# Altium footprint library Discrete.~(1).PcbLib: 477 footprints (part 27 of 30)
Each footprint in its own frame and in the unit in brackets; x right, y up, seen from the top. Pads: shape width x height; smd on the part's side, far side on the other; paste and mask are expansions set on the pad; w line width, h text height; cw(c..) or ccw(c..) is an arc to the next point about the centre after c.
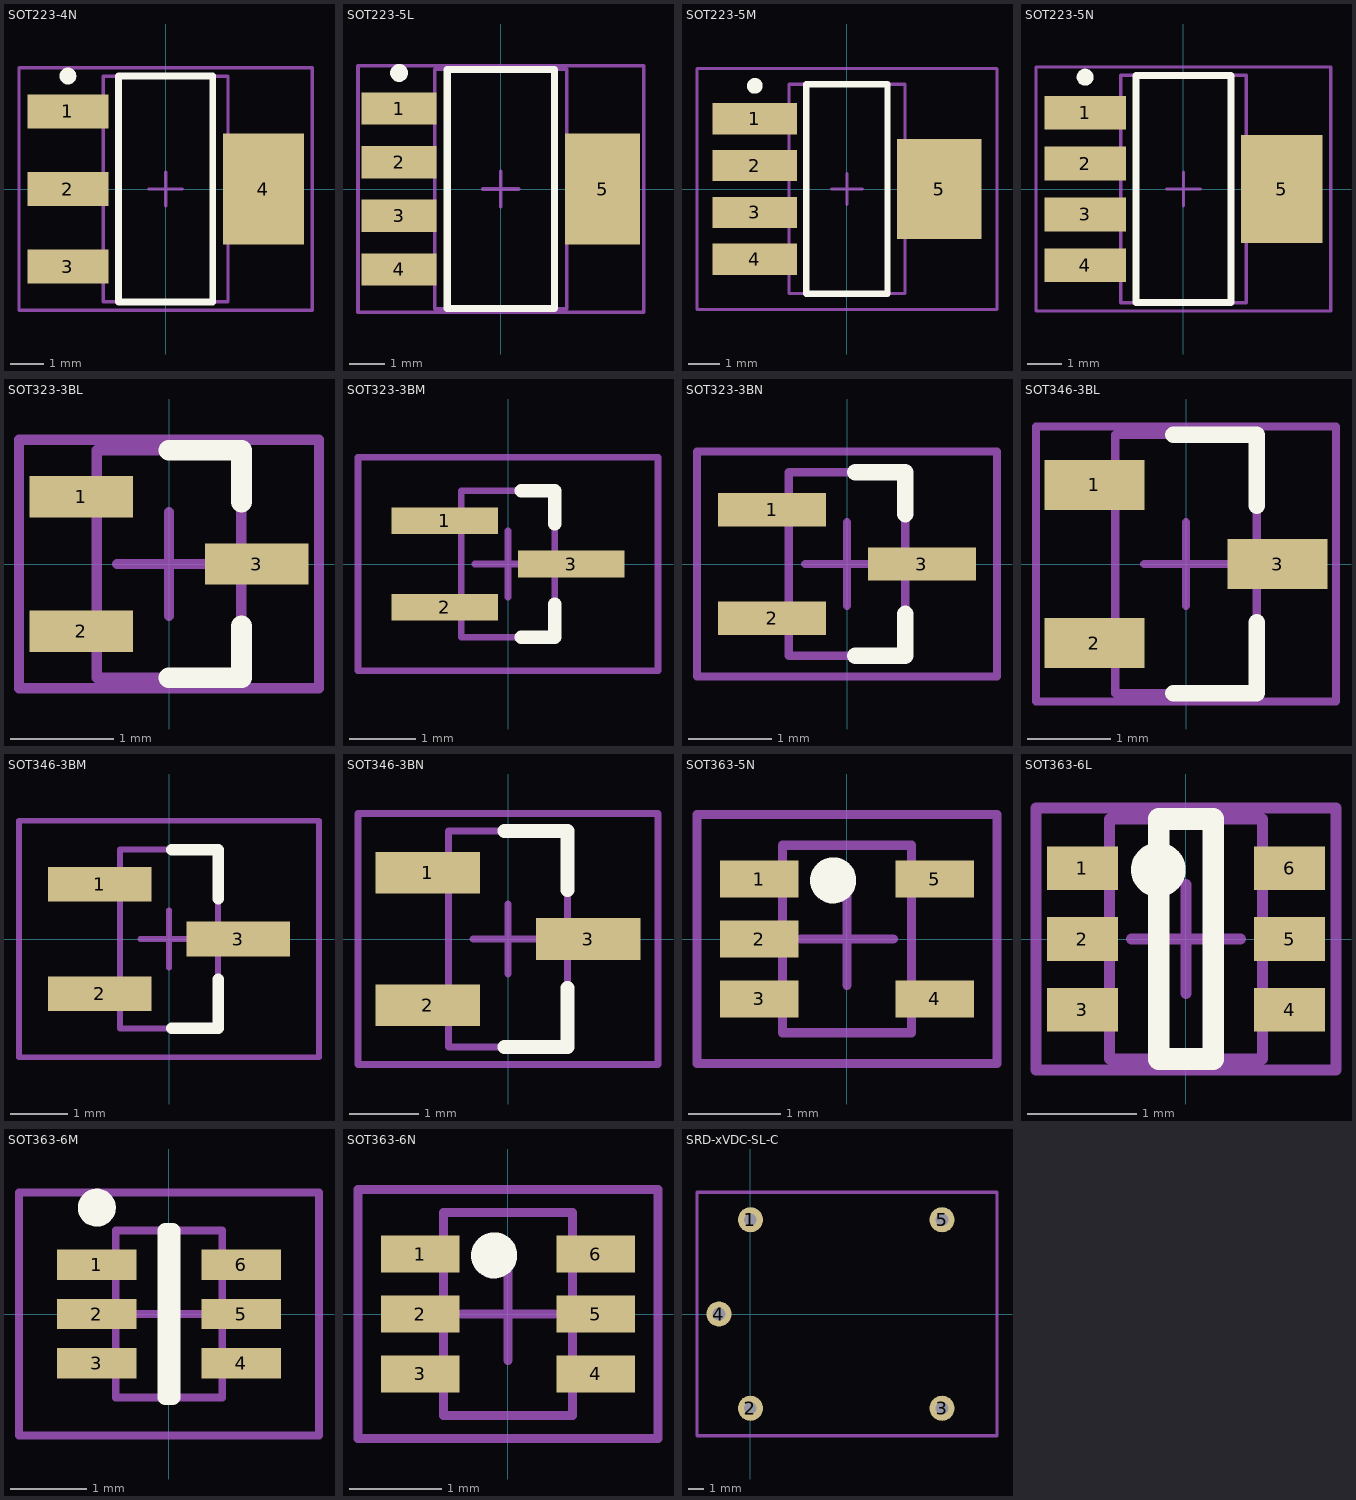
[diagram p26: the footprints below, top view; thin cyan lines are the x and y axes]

## SOT223-4N [mm] "SOT223/SC73, 4-Leads, Body 6.5x3.5mm, Pitch 2.3mm, Lead Span 7mm, IPC Medium Density"
height 1.8
pads (4):
  rect 2.4x1 smd: 1(-2.9,2.3) 2(-2.9,0) 3(-2.9,-2.3)
  rect 2.4x3.3 smd: 4(2.9,0)
Top Overlay:
  circle w0.25: c-2.9,3.35 r0.125
  lines w0.2: -1.4,-3.35 -1.4,3.35 1.4,3.35 1.4,-3.35 -1.4,-3.35
Mechanical 13:
  lines w0.1: -1.85,-3.35 -1.85,3.35 1.85,3.35 1.85,-3.35 -1.85,-3.35
Mechanical 15:
  lines w0.1: -0.5,0 0.5,0 ; 0,-0.5 0,0.5 ; -4.35,-3.6 -4.35,3.6 4.35,3.6 4.35,-3.6 -4.35,-3.6
3D body "SOT223.STEP": height 1.74, standoff 0.09, extent -3.551,-3.275 3.449,3.225

## SOT223-5L [mm] "SOT223, 5-Leads, Body 6.5x3.5mm, Pitch 1.5mm, Lead Span 7mm, IPC High Density"
height 1.8
pads (5):
  rect 2.1x0.9 smd: 1(-2.85,2.25) 2(-2.85,0.75) 3(-2.85,-0.75) 4(-2.85,-2.25)
  rect 2.1x3.1 smd: 5(2.85,0)
Top Overlay:
  circle w0.25: c-2.85,3.25 r0.125
  lines w0.2: -1.5,-3.35 1.5,-3.35 1.5,3.35 -1.5,3.35 -1.5,-3.35
Mechanical 13:
  lines w0.1: -1.85,-3.35 1.85,-3.35 1.85,3.35 -1.85,3.35 -1.85,-3.35
Mechanical 15:
  lines w0.1: -0.5,0 0.5,0 ; 0,-0.5 0,0.5 ; -4,-3.45 4,-3.45 4,3.45 -4,3.45 -4,-3.45
3D body: height 1.8, standoff 0, extent -1.85,-3.35 1.85,3.35

## SOT223-5M [mm] "SOT223, 5-Leads, Body 6.5x3.5mm, Pitch 1.5mm, Lead Span 7mm, IPC Low Density"
height 1.8
pads (5):
  rect 2.7x1 smd: 1(-2.95,2.25) 2(-2.95,0.75) 3(-2.95,-0.75) 4(-2.95,-2.25)
  rect 2.7x3.2 smd: 5(2.95,0)
Top Overlay:
  circle w0.25: c-2.95,3.3 r0.125
  lines w0.2: -1.3,-3.35 -1.3,3.35 1.3,3.35 1.3,-3.35 -1.3,-3.35
Mechanical 13:
  lines w0.1: -1.85,-3.35 -1.85,3.35 1.85,3.35 1.85,-3.35 -1.85,-3.35
Mechanical 15:
  lines w0.1: -0.5,0 0.5,0 ; 0,-0.5 0,0.5 ; -4.8,-3.85 -4.8,3.85 4.8,3.85 4.8,-3.85 -4.8,-3.85
3D body: height 1.8, standoff 0, extent -1.85,-3.35 1.85,3.35

## SOT223-5N [mm] "SOT223, 5-Leads, Body 6.5x3.5mm, Pitch 1.5mm, Lead Span 7mm, IPC Medium Density"
height 1.8
pads (5):
  rect 2.4x1 smd: 1(-2.9,2.25) 2(-2.9,0.75) 3(-2.9,-0.75) 4(-2.9,-2.25)
  rect 2.4x3.2 smd: 5(2.9,0)
Top Overlay:
  circle w0.25: c-2.9,3.3 r0.125
  lines w0.2: -1.4,-3.35 -1.4,3.35 1.4,3.35 1.4,-3.35 -1.4,-3.35
Mechanical 13:
  lines w0.1: -1.85,-3.35 -1.85,3.35 1.85,3.35 1.85,-3.35 -1.85,-3.35
Mechanical 15:
  lines w0.1: -0.5,0 0.5,0 ; 0,-0.5 0,0.5 ; -4.35,-3.6 -4.35,3.6 4.35,3.6 4.35,-3.6 -4.35,-3.6
3D body: height 1.8, standoff 0, extent -1.85,-3.35 1.85,3.35

## SOT323-3BL [mm] "SOT23, 3-Leads, Body 2x1.25mm, Pitch 0.65mm, Lead Span 2.1mm, IPC High Density"
height 1.1
pads (3):
  rect 1x0.4 smd: 1(-0.85,0.65) 2(-0.85,-0.65) 3(0.85,0)
Top Overlay:
  lines w0.2: 0,-1.1 0.7,-1.1 0.7,-0.6 ; 0,1.1 0.7,1.1 0.7,0.6
Mechanical 13:
  lines w0.1: -0.7,-1.1 0.7,-1.1 0.7,1.1 -0.7,1.1 -0.7,-1.1
Mechanical 15:
  lines w0.1: -0.5,0 0.5,0 ; 0,-0.5 0,0.5 ; -1.45,-1.2 1.45,-1.2 1.45,1.2 -1.45,1.2 -1.45,-1.2
3D body: height 1.1, standoff 0, extent -0.7,-1.1 0.7,1.1

## SOT323-3BM [mm] "SOT23, 3-Leads, Body 2x1.25mm, Pitch 0.65mm, Lead Span 2.1mm, IPC Low Density"
height 1.1
pads (3):
  rect 1.6x0.4 smd: 1(-0.95,0.65) 2(-0.95,-0.65) 3(0.95,0)
Top Overlay:
  lines w0.2: 0.2,-1.1 0.7,-1.1 0.7,-0.6 ; 0.2,1.1 0.7,1.1 0.7,0.6
Mechanical 13:
  lines w0.1: -0.7,-1.1 0.7,-1.1 0.7,1.1 -0.7,1.1 -0.7,-1.1
Mechanical 15:
  lines w0.1: -0.5,0 0.5,0 ; 0,-0.5 0,0.5 ; -2.25,-1.6 2.25,-1.6 2.25,1.6 -2.25,1.6 -2.25,-1.6
3D body: height 1.1, standoff 0, extent -0.7,-1.1 0.7,1.1

## SOT323-3BN [mm] "SOT23, 3-Leads, Body 2x1.25mm, Pitch 0.65mm, Lead Span 2.1mm, IPC Medium Density"
height 1.1
pads (3):
  rect 1.3x0.4 smd: 1(-0.9,0.65) 2(-0.9,-0.65) 3(0.9,0)
Top Overlay:
  lines w0.2: 0.1,-1.1 0.7,-1.1 0.7,-0.6 ; 0.1,1.1 0.7,1.1 0.7,0.6
Mechanical 13:
  lines w0.1: -0.7,-1.1 0.7,-1.1 0.7,1.1 -0.7,1.1 -0.7,-1.1
Mechanical 15:
  lines w0.1: -0.5,0 0.5,0 ; 0,-0.5 0,0.5 ; -1.8,-1.35 1.8,-1.35 1.8,1.35 -1.8,1.35 -1.8,-1.35
3D body: height 1.1, standoff 0, extent -0.7,-1.1 0.7,1.1

## SOT346-3BL [mm] "SOT346, 3-Leads, Body 2.9x1.5mm, Pitch 0.95mm, Lead Span 2.8mm , IPC High Density"
height 1.3
pads (3):
  rect 1.2x0.6 smd: 1(-1.1,0.95) 2(-1.1,-0.95) 3(1.1,0)
Top Overlay:
  lines w0.2: -0.15,-1.55 0.85,-1.55 0.85,-0.7 ; -0.15,1.55 0.85,1.55 0.85,0.7
Mechanical 13:
  lines w0.1: -0.85,-1.55 -0.85,1.55 0.85,1.55 0.85,-1.55 -0.85,-1.55
Mechanical 15:
  lines w0.1: -0.5,0 0.5,0 ; 0,-0.5 0,0.5 ; -1.8,-1.65 -1.8,1.65 1.8,1.65 1.8,-1.65 -1.8,-1.65
3D body: height 1.3, standoff 0, extent -0.85,-1.55 0.85,1.55

## SOT346-3BM [mm] "SOT346, 3-Leads, Body 2.9x1.5mm, Pitch 0.95mm, Lead Span 2.8mm ,IPC Low Density"
height 1.3
pads (3):
  rect 1.8x0.6 smd: 1(-1.2,0.95) 2(-1.2,-0.95) 3(1.2,0)
Top Overlay:
  lines w0.2: 0.05,-1.55 0.85,-1.55 0.85,-0.7 ; 0.05,1.55 0.85,1.55 0.85,0.7
Mechanical 13:
  lines w0.1: -0.85,-1.55 0.85,-1.55 0.85,1.55 -0.85,1.55 -0.85,-1.55
Mechanical 15:
  lines w0.1: -0.5,0 0.5,0 ; 0,-0.5 0,0.5 ; -2.6,-2.05 2.6,-2.05 2.6,2.05 -2.6,2.05 -2.6,-2.05
3D body: height 1.3, standoff 0, extent -0.85,-1.55 0.85,1.55

## SOT346-3BN [mm] "SOT346, 3-Leads, Body 2.9x1.5mm, Pitch 0.95mm, Lead Span 2.8mm,PC Medium Density"
height 1.3
pads (3):
  rect 1.5x0.6 smd: 1(-1.15,0.95) 2(-1.15,-0.95) 3(1.15,0)
Top Overlay:
  lines w0.2: -0.05,-1.55 0.85,-1.55 0.85,-0.7 ; -0.05,1.55 0.85,1.55 0.85,0.7
Mechanical 13:
  lines w0.1: -0.85,-1.55 -0.85,1.55 0.85,1.55 0.85,-1.55 -0.85,-1.55
Mechanical 15:
  lines w0.1: -0.5,0 0.5,0 ; 0,-0.5 0,0.5 ; -2.15,-1.8 -2.15,1.8 2.15,1.8 2.15,-1.8 -2.15,-1.8
3D body: height 1.3, standoff 0, extent -0.85,-1.55 0.85,1.55

## SOT363-5N [mm] "SOT363, 6-Leads, Body 2x1.3mm, Pitch 0.65mm, Lead Span 2.1mm, IPC Medium Density"
height 1
pads (5):
  rect 0.85x0.4 smd: 1(-0.95,0.65) 2(-0.95,0) 3(-0.95,-0.65) 4(0.95,-0.65) 5(0.95,0.65)
Top Overlay:
  circle w0.25: c-0.15,0.635 r0.125
Mechanical 13:
  lines w0.1: -0.7,-1.016 -0.7,1.016 0.7,1.016 0.7,-1.016 -0.7,-1.016
Mechanical 15:
  lines w0.1: -0.5,0 0.5,0 ; 0,-0.5 0,0.5 ; -1.625,-1.35 -1.625,1.35 1.625,1.35 1.625,-1.35 -1.625,-1.35
3D body "User Library-SC70-5-1.STEP": height 0.95, standoff 0, extent -1.05,-1 1.05,1

## SOT363-6L [mm] "SOT363, 6-Leads, Body 2x1.3mm, Pitch 0.65mm, Lead Span 2.1mm, IPC High Density"
height 1
pads (6):
  rect 0.65x0.4 smd: 1(-0.95,0.65) 2(-0.95,0) 3(-0.95,-0.65) 4(0.95,-0.65) 5(0.95,0) 6(0.95,0.65)
Top Overlay:
  circle w0.25: c-0.254,0.635 r0.125
  lines w0.2: -0.25,-1.1 -0.25,1.1 0.25,1.1 0.25,-1.1 -0.25,-1.1
Mechanical 13:
  lines w0.1: -0.7,-1.1 0.7,-1.1 0.7,1.1 -0.7,1.1 -0.7,-1.1
Mechanical 15:
  lines w0.1: -0.5,0 0.5,0 ; 0,-0.5 0,0.5 ; -1.375,-1.2 1.375,-1.2 1.375,1.2 -1.375,1.2 -1.375,-1.2
3D body "User Library-sot363.STEP": height 1, standoff 0, extent -1.15,-1.05 1.15,1.05

## SOT363-6M [mm]
pads (6):
  rect 1.05x0.4 smd: 1(-0.95,0.65) 2(-0.95,0) 3(-0.95,-0.65) 4(0.95,-0.65) 5(0.95,0) 6(0.95,0.65)
Top Overlay:
  circle w0.25: c-0.95,1.4 r0.125
  lines w0.2: -0.05,-1.1 -0.05,1.1 0.05,1.1 0.05,-1.1 -0.05,-1.1
Mechanical 13:
  lines w0.1: -0.7,-1.1 0.7,-1.1 0.7,1.1 -0.7,1.1 -0.7,-1.1
Mechanical 15:
  lines w0.1: -0.5,0 0.5,0 ; 0,-0.5 0,0.5 ; -1.975,-1.6 1.975,-1.6 1.975,1.6 -1.975,1.6 -1.975,-1.6
3D body "User Library-sot363.STEP": height 1, standoff 0, extent -1.15,-1.05 1.15,1.05

## SOT363-6N [mm] "SOT363, 6-Leads, Body 2x1.3mm, Pitch 0.65mm, Lead Span 2.1mm, IPC Medium Density"
height 1
pads (6):
  rect 0.85x0.4 smd: 1(-0.95,0.65) 2(-0.95,0) 3(-0.95,-0.65) 4(0.95,-0.65) 5(0.95,0) 6(0.95,0.65)
Top Overlay:
  circle w0.25: c-0.15,0.635 r0.125
Mechanical 13:
  lines w0.1: -0.7,-1.1 0.7,-1.1 0.7,1.1 -0.7,1.1 -0.7,-1.1
Mechanical 15:
  lines w0.1: -0.5,0 0.5,0 ; 0,-0.5 0,0.5 ; -1.625,-1.35 1.625,-1.35 1.625,1.35 -1.625,1.35 -1.625,-1.35
3D body "User Library-sot363.STEP": height 1, standoff 0, extent -1.15,-1.05 1.15,1.05

## SPDT_6X12 [mm]

## SRD-xVDC-SL-C [mm]
pads (5):
  round 1.6 hole 0.8: 1(0,6) 2(0,-6) 3(12.2,-6) 4(-2,0) 5(12.2,6)
Mechanical 13:
  lines w0.203: -3.4,-7.75 -3.4,7.75 15.7,7.75 15.7,-7.75 -3.4,-7.75
3D body: height 15.3, standoff 0, extent -3.4,-7.75 15.7,7.75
